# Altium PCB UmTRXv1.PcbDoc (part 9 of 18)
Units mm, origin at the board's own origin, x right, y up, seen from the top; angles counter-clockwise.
Board outline 172 x 113 mm, 6 copper layers (Top Layer, GND, MidLayer1, Mid-Layer 2, InternalPlane2, Bottom Layer); 766 components, 613 nets, 3008 pads, 1360 vias.
Unrouted connection lines stored in the file: 2.
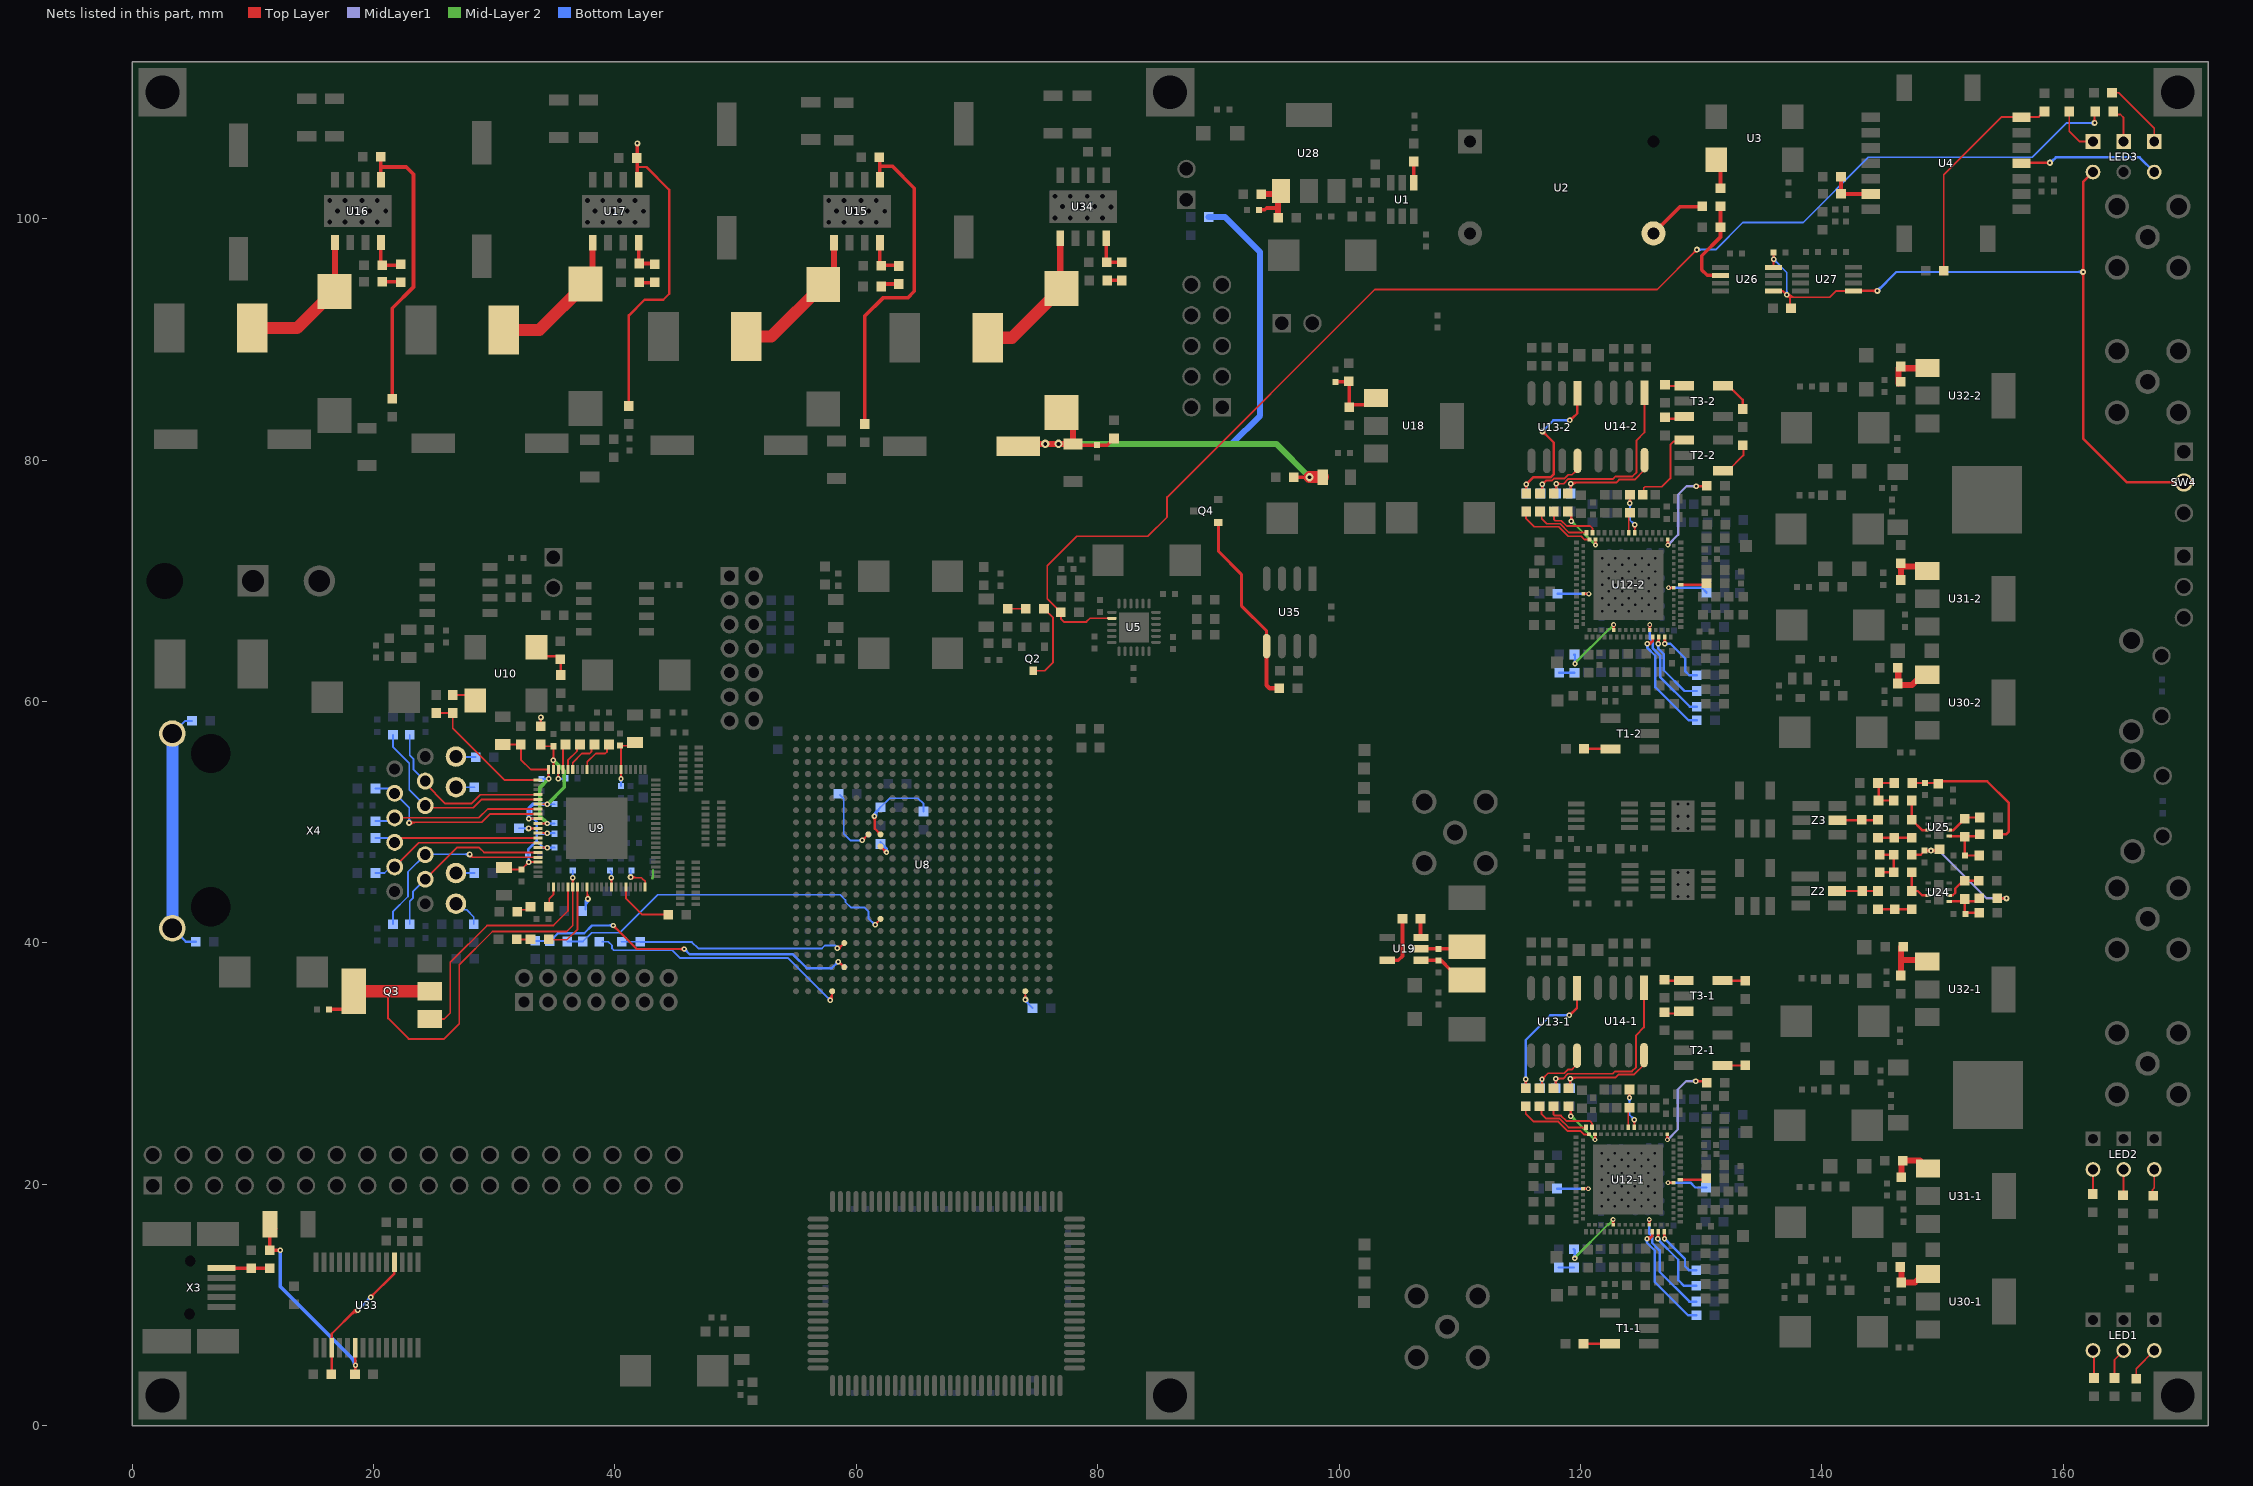
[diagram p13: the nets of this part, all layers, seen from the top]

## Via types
v1: diameter 0.45, hole 0.2, Top Layer to Bottom Layer, tented both sides, 554 vias
v2: diameter 0.5, hole 0.2, Top Layer to Bottom Layer, tented both sides, 468 vias
v3: diameter 0.7, hole 0.3, Top Layer to Bottom Layer, tented both sides, 206 vias
v4: diameter 0.4, hole 0.2, Top Layer to Bottom Layer, tented both sides, 82 vias
v5: diameter 0.8, hole 0.3, Top Layer to Bottom Layer, tented both sides, 16 vias
v6: diameter 0.6, hole 0.25, Top Layer to Bottom Layer, tented both sides, 16 vias
v7: diameter 0.5, hole 0.3, Top Layer to Bottom Layer, tented both sides, 8 vias
v8: diameter 0.7, hole 0.3, Top Layer to Bottom Layer, 4 vias
v9: diameter 0.6, hole 0.3, Top Layer to Bottom Layer, tented both sides, 4 vias
v10: diameter 0.5, hole 0.2, Top Layer to Bottom Layer, 2 vias

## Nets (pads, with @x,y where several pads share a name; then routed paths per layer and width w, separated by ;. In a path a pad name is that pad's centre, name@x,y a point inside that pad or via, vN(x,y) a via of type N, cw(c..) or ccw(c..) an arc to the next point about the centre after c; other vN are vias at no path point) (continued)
NetC107-2_2: C107-2.2 T2-2.3 | length 7.2
  Top Layer w0.15: C107-2.2@125.15,77.15 125.25,77.25 125.25,77.704 125.346,77.8 126.75,77.8 127.45,78.5 127.45,81.3 127.7,81.55 128.48,81.55 T2-2.3@128.6,81.67
NetC110-1_1: C110-1.1 T1-1.4 | length 2.2
  Top Layer w0.2: C110-1.1@120.257,6.788 T1-1.4@122.461,6.788
NetC110-2_1: C110-2.1 T1-2.4 | length 2.2
  Top Layer w0.2: C110-2.1@120.296,56.08 T1-2.4@122.5,56.08
NetC111-1_2: C111-1.2 T2-1.6 | length 1.9
  Top Layer w0.15: T2-1.6@131.761,29.838 131.781,29.858 C111-1.2@133.661,29.858
NetC111-2_2: C111-2.2 T2-2.6 | length 3
  Top Layer w0.15: T2-2.6@131.8,79.13 131.82,79.15 132.25,79.15 133.5,80.4 C111-2.2@133.5,81.2
NetC112-1_1: C112-1.1 T3-1.4 | length 1.9
  Top Layer w0.2: T3-1.4@131.761,36.878 133.641,36.878 C112-1.1@133.661,36.858
NetC112-2_1: C112-2.1 T3-2.4 | length 2.8
  Top Layer w0.2: T3-2.4@131.8,86.17 132.28,86.17 133.45,85 C112-2.1@133.45,84.3
NetC113_1: C113.1 C131.1 C261.1 C269.1 L34.1 L35.1 R170.1 R172.1 | length 75.3
  Top Layer w0.3: C261.1@78.054,81.246 C113.1@79.946,81.246 80.796,81.246 R170.1@81.35,81.8 ; C269.1@96.25,78.6 v3(97.55,78.6) ; v3@97.409,78.459 ccw(c97.067,78.117) 97.067,78.6 ccw(c97.067,79.083) v3@97.409,78.741
  Top Layer w0.5: C131.1@73.4,81.15 73.6,81.35 C261.1@77.95,81.35 ; L35.1@77,83.95 77.95,83 C261.1@77.95,81.35 ; C261.1@78.054,81.246 C261.1@77.95,81.35
  Top Layer w1: v3(97.55,78.6) L34.1@98.65,78.6
  Mid-Layer 2 w0.5: v3(75.65,81.35) v3(76.75,81.35) 94.8,81.35 v3(97.55,78.6)
  Bottom Layer w0.5: v3(75.65,81.35) v3(76.75,81.35) 91.1,81.35 93.45,83.7 93.45,97.25 90.55,100.15 R172.1@89.2,100.15
NetC128_1: C128.1 C132.1 U15.4 | length 3.4
  Top Layer w0.3: U15.4@61.943,98.079 61.943,96.19 61.965,96.168 C128.1@61.984,96.187 ; C128.1@61.994,96.15 C132.1@63.45,96.15
NetC129_1: C129.1 C133.1 U16.4 | length 3.3
  Top Layer w0.3: C129.1@20.605,96.25 U16.4@20.605,98.095 ; C129.1@20.705,96.15 C133.1@22.2,96.15
NetC130_1: C130.1 C134.1 U17.4 | length 3.4
  Top Layer w0.3: C130.1@41.9,96.3 C130.1@41.953,96.3 ; U17.4@41.953,98.242 C130.1@41.953,96.3 ; C130.1@42,96.25 41.953,96.297 C130.1@41.953,96.3 ; C134.1@43.3,96.3 C130.1@42,96.3 C130.1@41.953,96.3
NetC132_2: C132.2 R131.1 | length 1.3
  Top Layer w0.3: R131.1@62.15,94.6 C132.2@63.4,94.6
NetC133_2: C133.2 R132.1 | length 1.3
  Top Layer w0.3: R132.1@20.751,94.8 C133.2@22.1,94.8
NetC134_2: C134.2 R133.1 | length 1.3
  Top Layer w0.3: R133.1@41.95,94.7 C134.2@43.3,94.7
NetC135_1: C135.1 R134.2 R135.1 U18.1 | length 5.8
  Top Layer w0.3: C135.1@99.7,86.5 100.75,86.5 R135.1@100.8,86.55 100.85,86.5 R134.2@100.85,84.4 101.05,84.6 102.5,84.6 U18.1@103.05,85.15
NetC149_2: C149.2 L39.2 U19.2 | length 4.1
  Top Layer w0.3: U19.2@106.783,39.513 109.795,39.513 L39.2@110.55,40.268
NetC155_1: C155.1 L44.1 U19.1 | length 4.1
  Top Layer w0.3: U19.1@106.783,38.563 108.437,38.563 109.218,37.782 L44.1@110.55,37.782
NetC170_1: C170.1 U19.5 | length 4.5
  Top Layer w0.3: U19.5@103.989,38.563 104.913,38.563 105.25,38.9 C170.1@105.25,42
NetC170_2: C170.2 U19.3 | length 1.6
  Top Layer w0.3: C170.2@106.75,42 106.75,40.496 U19.3@106.783,40.463
NetC214_2: C214.2 C236.1 C237.1 C238.1 C239.1 C280.1 C284.1 C286.2 L46.1 Q3.2 Q3.4 U9.6 U9.19 U9.48 U9.56 U9.63 | length 55.2
  Top Layer w0.1: U9.63@42.5,44.625 U9.63@42.5,44.975
  Top Layer w0.15: 21.2,36 21.2,33.75 22.9,32.05 25.85,32.05 27.1,33.3 27.1,38.2 29.85,40.95 36,40.95 36.5,41.45 U9.48@36.5,44.625 v1(36.5,45.4) ; v2@33.726,58.576 cw(c33.428,58.278) 33.85,58.278 cw(c34.272,58.278) v2@33.974,58.576 ; L46.1@33.85,57.95 33.85,58.65 33.8,58.7 v2(33.85,58.7) ; v1@35.194,53.706 ccw(c34.938,53.962) 35.3,53.962 ccw(c35.662,53.962) v1@35.406,53.706 ; v1(35.3,53.6) U9.19@35.3,54.375 ; v1@36.394,45.294 cw(c36.138,45.038) 36.5,45.038 cw(c36.862,45.038) v1@36.606,45.294 ; v1@39.594,45.294 cw(c39.338,45.038) 39.7,45.038 cw(c40.062,45.038) v1@39.806,45.294 ; U9.56@39.7,44.625 v1(39.7,45.4) ; v1@40.394,53.706 ccw(c40.138,53.962) 40.5,53.962 ccw(c40.862,53.962) v1@40.606,53.706 ; v1(40.5,53.6) U9.6@40.5,54.375 40.5,56.25 C286.2@40.4,56.35 41.4,56.35 C284.1@41.65,56.6 ; v2(41.3,45.45) 41.3,45.4 42.199,45.4 42.274,45.325 ; v2@41.424,45.326 cw(c41.602,45.148) 41.602,45.4 ; v2@41.424,45.574 ccw(c41.843,45.993) 41.843,45.4 ; 42.275,45.325 42.5,45.1 U9.63@42.5,44.975
  Top Layer w0.3: C214.2@16.3,34.5 Q3.4@17.5,34.5
  Top Layer w1: Q3.4@18.35,36 21.2,36 Q3.2@24.65,36
  Mid-Layer 2 w0.2: 43.1,45.35 43.15,45.4 43.15,46.05
  Bottom Layer w0.15: v1(35.3,53.6) 35.85,53.6 C237.1@35.9,53.65 ; v1@35.406,53.494 cw(c35.662,53.238) 35.662,53.6 cw(c35.662,53.962) v1@35.406,53.706 ; v1@36.394,45.506 ccw(c36.138,45.762) 36.5,45.762 ccw(c36.862,45.762) v1@36.606,45.506 ; v1(36.5,45.4) C238.1@36.5,46 ; v1@39.594,45.506 ccw(c39.338,45.762) 39.7,45.762 ccw(c40.062,45.762) v1@39.806,45.506 ; C239.1@39.6,46 39.7,45.9 v1(39.7,45.4) ; v1@40.394,53.494 cw(c40.138,53.238) 40.5,53.238 cw(c40.862,53.238) v1@40.606,53.494 ; C236.1@40.5,53 v1(40.5,53.6) ; v2@41.176,45.574 ccw(c40.878,45.872) 41.3,45.872 ccw(c41.723,45.873) v2@41.424,45.574 ; v2(41.3,45.45) C280.1@41.3,46.05
NetC240_1: C240.1 C241.1 C242.1 C243.1 C244.1 C245.1 C285.1 C287.2 L46.2 U9.20 U9.27 U9.30 U9.33 U9.36 U9.39 | length 33.4
  Top Layer w0.15: C285.1@30.8,46.05 30.85,46.1 C287.2@32.25,46.1 v1(32.85,46.7) U9.39@33.625,46.7 ; v1@32.7,46.7 cw(c32.338,46.7) 32.594,46.444 cw(c32.85,46.188) v1@32.85,46.55 ; v1(32.85,50.3) U9.30@33.625,50.3 ; v1@32.956,46.594 cw(c33.212,46.338) 33.212,46.7 cw(c33.212,47.062) v1@32.956,46.806 ; v1@32.956,50.194 cw(c33.212,49.938) 33.212,50.3 cw(c33.212,50.662) v1@32.956,50.406 ; U9.36@33.625,47.9 v1(34.4,47.9) ; U9.33@33.625,49.1 v1(34.4,49.1) ; U9.27@33.625,51.5 v1(34.4,51.5) ; L46.2@33.85,56.45 34,56.3 C240.1@34.9,56.3 v1(34.9,55.15) U9.20@34.9,54.375 ; v1@34.294,47.794 ccw(c34.038,47.538) 34.038,47.9 ccw(c34.038,48.262) v1@34.294,48.006 ; v1@34.294,48.994 ccw(c34.038,48.738) 34.038,49.1 ccw(c34.038,49.462) v1@34.294,49.206 ; v1@34.294,51.394 ccw(c34.038,51.138) 34.038,51.5 ccw(c34.038,51.862) v1@34.294,51.606 ; v1@34.794,55.044 cw(c34.538,54.788) 34.9,54.788 cw(c35.262,54.788) v1@35.006,55.044 ; v1@34.794,55.256 ccw(c34.538,55.512) 34.9,55.512 ccw(c35.262,55.512) v1@35.006,55.256
  Mid-Layer 2 w0.3: v1(34.4,51.5) 35.8,52.9 35.8,54.25 v1(34.9,55.15)
  Bottom Layer w0.15: v1@32.744,46.806 ccw(c32.488,47.062) 32.85,47.062 ccw(c33.212,47.062) v1@32.956,46.806 ; v1@32.744,50.406 ccw(c32.488,50.662) 32.85,50.662 ccw(c33.212,50.662) v1@32.956,50.406 ; C245.1@32.8,47.3 32.85,47.25 v1(32.85,46.7) ; v1(32.85,50.3) 32.85,50.75 C242.1@32.9,50.8 ; v1(34.4,47.9) C244.1@35,47.9 ; v1(34.4,49.1) C243.1@35,49.1 ; v1(34.4,51.5) C241.1@35,51.5 ; v1@34.506,47.794 cw(c34.762,47.538) 34.762,47.9 cw(c34.762,48.262) v1@34.506,48.006 ; v1@34.506,48.994 cw(c34.762,48.738) 34.762,49.1 cw(c34.762,49.462) v1@34.506,49.206 ; v1@34.506,51.394 cw(c34.762,51.138) 34.762,51.5 cw(c34.762,51.862) v1@34.506,51.606
  Bottom Layer w0.2: C245.1@32.8,47.3 32.8,47.75 33.5,48.45 ; v1(32.85,50.3) 33.25,50.3 33.5,50.05 33.5,49.05 ; v1@32.938,50.212 cw(c33.152,49.998) 33.152,50.3 cw(c33.152,50.602) v1@32.938,50.388 ; 33.978,49.05 ccw(c33.978,49.522) v1@34.312,49.188 ; v1@34.312,47.812 ccw(c34.098,47.598) 34.098,47.9 ccw(c34.098,48.202) v1@34.312,47.988 ; v1(34.4,47.9) 34.05,47.9 33.5,48.45 ; v1(34.4,49.1) 34.35,49.05 33.5,49.05 ; 33.5,48.45 33.5,49.05
  Bottom Layer w0.3: C242.1@32.9,50.8 32.9,51.2 33.2,51.5 v1(34.4,51.5)
NetC266_1: C266.1 C267.1 U34.4 | length 3.3
  Top Layer w0.3: U34.4@80.703,98.392 80.703,96.447 C266.1@80.75,96.4 C267.1@82,96.4
NetC267_2: C267.2 R169.1 | length 1.2
  Top Layer w0.3: R169.1@80.8,94.9 C267.2@82,94.9
NetC278_1: C278.1 R5.2 R8.1 U28.1 | length 5.4
  Top Layer w0.3: C278.1@93.35,100.75 93.85,100.75 94,100.9 94.95,100.9
  Top Layer w0.5: R5.2@93.55,102.05 U28.1@94.95,102.05 ; R8.1@94.95,100.1 94.95,100.9 U28.1@94.95,102.05 ; U28.1@95.2,102.3 U28.1@94.95,102.05
NetC281_1: C281.1 C282.1 C283.1 L45.2 U9.21 U9.31 | length 14.7
  Top Layer w0.15: C283.1@30.7,56.45 L45.2@32.2,56.45 32.2,55.2 33.025,54.375 U9.21@34.5,54.375 v1(34.5,53.6) ; U9.31@33.625,49.9 v1(34.4,49.9) ; v1@34.294,49.794 ccw(c34.038,49.538) 34.038,49.9 ccw(c34.038,50.262) v1@34.294,50.006 ; v1@34.394,53.706 ccw(c34.138,53.962) 34.5,53.962 ccw(c34.862,53.962) v1@34.606,53.706
  Mid-Layer 2 w0.3: v1(34.4,49.9) 33.75,50.55 33.75,52.85 v1(34.5,53.6)
  Bottom Layer w0.15: C281.1@33.9,53.6 v1(34.5,53.6) ; v1@34.394,53.494 ccw(c34.138,53.238) 34.138,53.6 ccw(c34.138,53.962) v1@34.394,53.706 ; v1(34.4,49.9) C282.1@35,49.9 ; v1@34.506,49.794 cw(c34.762,49.538) 34.762,49.9 cw(c34.762,50.262) v1@34.506,50.006
NetC298_2: C298.2 L49.2 R143.1 R147.1 | length 14
  Top Layer w0.2: R147.1@147.401,47.306 148.201,47.306 148.551,47.656 v2(149.05,47.656) 149.651,47.656 L49.2@149.751,47.756 ; v2@148.944,47.55 ccw(c148.688,47.294) 148.688,47.656 ccw(c148.688,48.018) v2@148.944,47.762 ; v2@149.156,47.55 cw(c149.412,47.294) 149.412,47.656 cw(c149.412,48.018) v2@149.156,47.762 ; R143.1@154.55,43.7 v2(155.3,43.7) ; v2@155.194,43.594 ccw(c154.938,43.338) 154.938,43.7 ccw(c154.938,44.062) v2@155.194,43.806
  MidLayer1 w0.2: v2(149.05,47.656) 149.694,47.656 153.65,43.7 v2(155.3,43.7) ; v2@149.156,47.55 cw(c149.412,47.294) 149.412,47.656 cw(c149.412,48.018) v2@149.156,47.762 ; v2@155.194,43.594 ccw(c154.938,43.338) 154.938,43.7 ccw(c154.938,44.062) v2@155.194,43.806
NetC299_2: C299.2 L50.2 R145.1 R148.1 | length 12.3
  Top Layer w0.2: R148.1@147.501,53.256 C299.2@148.551,53.256 149.401,53.256 L50.2@149.651,53.006 ; L50.2@149.65,53.2 149.85,53.4 153.7,53.4 155.5,51.6 155.5,49.25 155.25,49 R145.1@154.6,49
NetC300_1: C300.1 R141.2 R144.2 | length 2.8
  Top Layer w0.2: R141.2@144.651,42.806 R144.2@146.051,42.806 C300.1@147.451,42.806
NetC300_2: C300.2 L51.2 U24.7 | length 3.1
  Top Layer w0.2: L51.2@147.451,45.856 C300.2@147.451,44.306 147.944,44.306 148.3,43.95 U24.7@148.825,43.95
NetC301_1: C301.1 R142.2 R146.2 | length 2.8
  Top Layer w0.2: R142.2@144.651,48.706 R146.2@146.001,48.706 C301.1@147.451,48.706
NetC301_2: C301.2 L52.2 U25.7 | length 3.3
  Top Layer w0.2: L52.2@147.451,51.806 C301.2@147.451,50.206 148.301,49.356 U25.7@148.826,49.356
NetC302_1: C302.1 C304.1 L51.1 R147.2 | length 3.7
  Top Layer w0.2: C302.1@144.801,45.856 L51.1@145.951,45.856 145.951,47.299 R147.2@145.95,47.3 145.944,47.306 C304.1@144.801,47.306
NetC303_1: C303.1 C305.1 L52.1 R148.2 | length 4.1
  Top Layer w0.2: L52.1@145.951,51.806 C303.1@144.701,51.806 144.701,53.206 C305.1@144.651,53.256 R148.2@146.001,53.256
NetC306_2: C306.2 C310.1 L53.1 R143.2 U24.1 | length 5
  Top Layer w0.2: U24.1@150.575,43.45 L53.1@151.85,43.45 ; L53.1@151.85,43.65 L53.1@151.85,43.45 ; C310.1@153.05,42.5 152,42.5 C306.2@151.9,42.4 151.85,42.45 L53.1@151.85,43.45 ; R143.2@153.05,43.7 152.8,43.45 L53.1@151.85,43.45
NetC307_1: C307.1 L53.2 U24.2 | length 3.1
  Top Layer w0.2: U24.2@150.575,43.95 150.85,43.95 151.05,44.15 151.05,44.5 151.7,45.15 L53.2@151.85,45.15 C307.1@153,45.15
NetC308_2: C308.2 C311.1 L54.1 R145.2 U25.1 | length 5.3
  Top Layer w0.2: U25.1@150.576,48.856 152.956,48.856 R145.2@153.1,49 ; L54.1@151.85,48.8 151.85,47.257 C308.2@151.851,47.256 151.857,47.25 C311.1@153.05,47.25
NetC309_1: C309.1 L54.2 U25.2 | length 3
  Top Layer w0.2: U25.2@150.576,49.356 150.906,49.356 L54.2@151.85,50.3 151.95,50.4 C309.1@153.1,50.4
NetC313_2: C313.2 LED3.4 R153.2 SW4.2 U26.5 U26.8 U27.5 | length 71.7
  Top Layer w0.15: C313.2@135.9,97.15 136.008,97.042 v1(136.008,96.65) U26.8@136.008,95.97 ; v1@135.902,96.544 cw(c135.645,96.288) 136.008,96.288 cw(c136.37,96.288) v1@136.114,96.544 ; v1@135.902,96.756 ccw(c135.645,97.012) 136.008,97.012 ccw(c136.37,97.012) v1@136.114,96.756 ; U26.5@136.008,94.021 136.779,94.021 v1(137.1,93.7) ; v1@136.95,93.7 ccw(c136.588,93.7) 136.844,93.956 ccw(c137.1,94.212) v1@137.1,93.85 ; v1@137.128,93.553 cw(c137.164,93.365) 137.3,93.5 ; v1@137.206,93.806 ccw(c137.945,94.545) 137.945,93.5 ; v1@137.247,93.672 ccw(c137.435,93.636) 137.3,93.5 ; R153.2@137.36,92.8 137.36,93.46 ; 137.583,93.5 cw(c137.583,94.183) v1(137.1,93.7) ; U27.5@142.621,94.036 141.186,94.036 140.65,93.5 137.3,93.5 ; v1(137.1,93.7) 137.3,93.5
  Top Layer w0.2: U27.5@142.621,94.036 v2(144.6,94.036) ; v2@144.494,93.93 ccw(c144.238,93.674) 144.238,94.036 ccw(c144.238,94.398) v2@144.494,94.142 ; v2@161.544,95.494 cw(c161.288,95.238) 161.65,95.238 cw(c162.012,95.238) v2@161.756,95.494 ; v2@161.544,95.706 ccw(c161.288,95.962) 161.65,95.962 ccw(c162.012,95.962) v2@161.756,95.706 ; LED3.4@162.47,103.88 161.65,103.06 v2(161.65,95.6) 161.65,81.8 165.29,78.16 SW4.2@170,78.16
  Bottom Layer w0.15: v1@136.008,96.5 cw(c136.008,96.138) 136.264,96.394 cw(c136.52,96.65) v1@136.158,96.65 ; v1(136.008,96.65) 137.1,95.558 v1(137.1,93.7) ; v1@136.994,93.806 ccw(c136.738,94.062) 137.1,94.062 ccw(c137.462,94.062) v1@137.206,93.806
  Bottom Layer w0.2: v2(144.6,94.036) 146.164,95.6 v2(161.65,95.6) ; v2@144.6,94.186 ccw(c144.6,94.548) 144.856,94.292 ccw(c145.112,94.036) v2@144.75,94.036 ; v2@161.544,95.494 ccw(c161.288,95.238) 161.288,95.6 ccw(c161.288,95.962) v2@161.544,95.706
NetC316_2: C316.2 L55.1 X3.1 | length 4
  Top Layer w0.3: X3.1@7.4,13.05 C316.2@9.85,13.05 L55.1@11.4,13.05
NetC317_1: C317.1 C318.2 L55.2 U33.20 | length 19.1
  Top Layer w0.2: v1@18.412,4.912 cw(c18.259,4.759) 18.475,4.759 ; v1@18.412,5.088 ccw(c18.259,5.241) 18.475,5.241 ; C318.2@18.45,4.25 18.475,4.275 U33.20@18.475,6.45 ; C318.2@18.475,4.638 cw(c18.862,4.638) v1@18.588,4.912 ; 18.475,5.362 ccw(c18.862,5.362) v1@18.588,5.088
  Top Layer w0.3: C317.1@11.9,16.325 11.4,15.825 L55.2@11.4,14.55 v1(12.25,14.55)
  Bottom Layer w0.3: v1(12.25,14.55) 12.25,11.55 18.45,5.35 18.45,5.05 v1(18.5,5) ; 18.16,5.64 cw(c17.52,5) v1@18.425,5 ; 18.45,5.302 ccw(c18.802,5.302) v1@18.553,5.053
NetC319_2: C319.2 U33.4 U33.17 | length 14.3
  Top Layer w0.2: C319.2@16.5,4.25 16.525,4.275 U33.17@16.525,6.45 16.525,7.625 18.45,9.55 ; 18.06,9.16 cw(c18.7,8.52) v1@18.7,9.425 ; 18.401,9.501 cw(c18.7,9.203) v1@18.7,9.625 ; v1@18.6,9.475 ccw(c18.45,9.363) 18.45,9.55 ; v1@18.6,9.625 cw(c18.45,9.737) 18.45,9.55 ; v1(18.7,9.55) 18.45,9.55 ; v1(19.75,10.65) 21.725,12.625 U33.4@21.725,13.55 ; v1@19.75,10.775 ccw(c19.75,11.077) 19.963,10.863 ccw(c20.177,10.65) v1@19.875,10.65
  Bottom Layer w0.2: v1(18.7,9.55) 18.7,9.6 v1(19.75,10.65) ; v1@18.825,9.55 cw(c19.247,9.55) 18.949,9.849 ; v1@19.625,10.65 cw(c19.323,10.65) 19.537,10.437 cw(c19.75,10.223) v1@19.75,10.525
NetD1_2: D1.2 L36.2 U15.1 | length 12
  Top Layer w0.5: L36.2@57.25,94.55 58.153,95.453 U15.1@58.153,98.029
  Top Layer w1: D1.2@50.879,90.25 52.95,90.25 L36.2@57.25,94.55
NetD2_2: D2.2 L37.2 U16.1 | length 12.3
  Top Layer w0.5: L37.2@16.793,94.093 U16.1@16.793,98.042
  Top Layer w1: D2.2@9.929,90.95 13.65,90.95 L37.2@16.793,94.093 ; L37.2@16.55,93.2 L37.2@16.55,93.4
NetD3_2: D3.2 L38.2 U17.1 | length 12
  Top Layer w0.5: L38.2@37.55,94.6 38.153,95.203 U17.1@38.153,98.029
  Top Layer w1: D3.2@30.779,90.8 33.75,90.8 L38.2@37.55,94.6
NetD4_2: D4.2 L35.2 U34.1 | length 12
  Top Layer w0.3: L35.2@76.893,94.357 L35.2@77,94.25
  Top Layer w0.5: L35.2@76.893,94.357 U34.1@76.893,98.392
  Top Layer w1: D4.2@70.879,90.15 72.9,90.15 L35.2@77,94.25
NetL32-1_2: L32-1.2 T3-1.1 | length 2
  Top Layer w0.2: L32-1.2@126.661,34.158 128.381,34.158 T3-1.1@128.561,34.338
NetL32-2_2: L32-2.2 T3-2.1 | length 2
  Top Layer w0.2: L32-2.2@126.7,83.45 128.42,83.45 T3-2.1@128.6,83.63
NetL33-1_2: L33-1.2 T3-1.3 | length 1.9
  Top Layer w0.2: L33-1.2@126.661,36.858 128.541,36.858 T3-1.3@128.561,36.878
NetL33-2_2: L33-2.2 T3-2.3 | length 1.9
  Top Layer w0.2: L33-2.2@126.7,86.15 128.58,86.15 T3-2.3@128.6,86.17
NetLED1_4: LED1.4 R35.2 | length 2.3
  Top Layer w0.15: LED1.4@162.47,6.23 162.55,6.15 R35.2@162.55,3.95
NetLED1_5: LED1.5 R34.2 | length 2.6
  Top Layer w0.15: R34.2@164.25,3.95 164.25,5.47 LED1.5@165.01,6.23
NetLED1_6: LED1.6 R33.2 | length 3
  Top Layer w0.15: R33.2@166.05,3.9 166.05,4.73 LED1.6@167.55,6.23
NetLED2_4: LED2.4 R38.2 | length 2
  Top Layer w0.15: R38.2@162.45,19.2 162.47,19.22 LED2.4@162.47,21.23
NetLED2_5: LED2.5 R37.2 | length 2.2
  Top Layer w0.15: R37.2@164.95,19.1 165.01,19.16 LED2.5@165.01,21.23
NetLED2_6: LED2.6 R36.2 | length 2.3
  Top Layer w0.15: R36.2@167.45,19.05 167.4,19.1 167.4,19.55 167.55,19.7 LED2.6@167.55,21.23
NetLED3_1: LED3.1 R1.2 | length 5.8
  Top Layer w0.15: R1.2@164.05,110.45 164.6,110.45 167.55,107.5 LED3.1@167.55,106.42
NetLED3_2: LED3.2 R13.1 | length 2.9
  Top Layer w0.15: R13.1@164.15,108.65 164.75,108.65 165.01,108.39 LED3.2@165.01,106.42
NetLED3_3: LED3.3 R162.2 | length 4
  Top Layer w0.15: R162.2@160.5,108.9 160.5,107.25 161.33,106.42 LED3.3@162.47,106.42
NetLED3_6: LED3.6 U4.4 | length 12.7
  Top Layer w0.2: U4.4@156.65,104.65 v2(158.9,104.65) ; v2@158.794,104.544 ccw(c158.538,104.288) 158.538,104.65 ccw(c158.538,105.012) v2@158.794,104.756
  Bottom Layer w0.2: v2(158.9,104.65) 158.95,104.65 159.4,105.1 166.33,105.1 LED3.6@167.55,103.88 ; v2@158.9,104.8 ccw(c158.9,105.283) 159.241,104.941 ; v2@159.05,104.65 cw(c159.291,104.65) 159.121,104.821
NetLED4_1: LED4.1 Q2.3 | length 6.7
  Top Layer w0.15: Q2.3@74.65,62.55 75.6,62.55 76.3,63.25 76.3,66.95 LED4.1@75.55,67.7
NetLED4_2: LED4.2 R29.2 | length 1.5
  Top Layer w0.15: R29.2@72.55,67.7 LED4.2@74.05,67.7
NetLED5_1: LED5.1 R55.1 | length 1.1
  Top Layer w0.15: LED5.1@31.9,42.6 32.05,42.75 32.75,42.75 R55.1@32.9,42.9
NetLED6_1: LED6.1 R57.1 | length 1.2
  Top Layer w0.15: LED6.1@31.85,40.3 R57.1@33,40.3
NetQ3_1: Q3.1 U9.47 | length 19.6
  Top Layer w0.15: Q3.1@24.65,33.7 25.85,33.7 26.35,34.2 26.35,38.4 29.4,41.45 34.9,41.45 36.1,42.65 U9.47@36.1,44.625
NetQ4_1: Q4.1 R174.2 U35.5 | length 16.5
  Top Layer w0.25: Q4.1@90,74.85 90,72.45 91.9,70.55 91.9,67.95 93.995,65.855 U35.5@93.995,64.603
  Top Layer w0.35: U35.5@93.995,64.603 93.995,61.355 94.25,61.1 R174.2@95.2,61.1
NetR4_1: R4.1 U1.1 | length 1.8
  Top Layer w0.3: R4.1@106.189,104.75 106.189,102.986 U1.1@106.19,102.985
NetR6_1: R6.1 U2.8 | length 5.4
  Top Layer w0.3: U2.8@126.3,98.55 U2.8@126.05,98.8 128.25,101 R6.1@130.2,101
NetR6_2: R6.2 R7.2 R12.2 U26.2 | length 7.7
  Top Layer w0.3: R7.2@131.6,101.05 R12.2@131.6,99.3 131.6,98.5 130.05,96.95 130.05,95.771 130.5,95.321 U26.2@131.608,95.321
NetR7_1: R7.1 U3.3 | length 1.4
  Top Layer w0.3: R7.1@131.6,102.55 U3.3@131.6,103.944
NetR9_2: R9.2 R10.1 U4.15 | length 3.9
  Top Layer w0.3: R9.2@141.586,103.503 141.593,103.496 R10.1@141.593,102.077 141.609,102.06 U4.15@144.05,102.06
NetR11_2: R11.2 R13.2 U5.8 | length 115.9
  Top Layer w0.15: U5.8@81.175,66.9 79.362,66.9 79.062,66.6 77.2,66.6 76.95,66.85 R11.2@76.95,67.4 76.15,68.2 75.825,68.525 75.825,71.275 78.25,73.7 84.15,73.7 85.75,75.3 85.75,76.95 102.95,94.15 126.35,94.15 v2(129.65,97.45) ; v2@129.475,97.45 cw(c129.053,97.45) 129.351,97.151 cw(c129.65,96.853) v2@129.65,97.275 ; v2@162.476,108.074 ccw(c162.178,108.372) 162.6,108.372 ccw(c163.022,108.372) v2@162.724,108.074 ; v2(162.6,107.95) 162.6,108.85 R13.2@162.65,108.9
  Bottom Layer w0.15: v2(129.65,97.45) 131.2,97.45 133.45,99.7 138.45,99.7 143.85,105.1 157.45,105.1 160.3,107.95 v2(162.6,107.95) ; v2@129.774,97.326 cw(c130.072,97.028) 130.072,97.45 cw(c130.072,97.872) v2@129.774,97.574 ; v2@162.476,107.826 ccw(c162.178,107.528) 162.178,107.95 ccw(c162.178,108.372) v2@162.476,108.074
NetR14_2: R14.2 R18.2 U8.C18 | length 30.8
  Top Layer w0.2: v1@39.85,41.325 cw(c39.85,41.023) 40.063,41.237 cw(c40.277,41.45) v1@39.975,41.45 ; v1(39.85,41.45) 41.8,39.5 v1(45.75,39.5) ; v1@45.662,39.412 ccw(c45.448,39.198) 45.448,39.5 ccw(c45.448,39.802) v1@45.662,39.588 ; v1@58.5,38.325 cw(c58.5,37.903) 58.799,38.201 ; v1(58.5,38.45) 58.55,38.5 58.55,38.45 U8.C18@59,38
  Bottom Layer w0.15: R18.2@33.388,40.171 34.565,40.171 R14.2@34.604,40.133
  Bottom Layer w0.2: R14.2@34.604,40.133 35.271,40.8 37.45,40.8 38.1,41.45 v1(39.85,41.45) ; v1@39.762,41.362 ccw(c39.548,41.148) 39.548,41.45 ccw(c39.548,41.752) v1@39.762,41.538 ; v1@45.75,39.375 cw(c45.75,39.073) 45.963,39.287 cw(c46.177,39.5) v1@45.875,39.5 ; v1(45.75,39.5) 46.2,39.05 54.75,39.05 55.886,37.914 57.964,37.914 v1(58.5,38.45) ; v1@58.375,38.45 cw(c58.073,38.45) 58.287,38.237 cw(c58.5,38.023) v1@58.5,38.325
NetR15_2: R15.2 R20.1 U8.G15 | length 30.4
  Top Layer w0.15: v1(61.55,41.5) 61.55,41.55 U8.G15@62,42 ; v1@61.55,41.65 ccw(c61.55,41.891) 61.721,41.721 ; v1@61.7,41.5 cw(c62.183,41.5) U8.G15@61.841,41.841
  Bottom Layer w0.15: R20.1@36.036,40.12 R15.2@37.341,40.12 38.071,40.85 40.4,40.85 43.55,44 58.65,44 59.1,43.55 59.1,43.384 59.534,42.95 60.666,42.95 61,42.616 61,42.05 v1(61.55,41.5) ; v1@61.4,41.5 ccw(c61.038,41.5) 61.294,41.756 ccw(c61.55,42.012) v1@61.55,41.65
NetR16_2: R16.2 U8.A19 | length 23.8
  Top Layer w0.15: v1@57.744,35.356 ccw(c57.126,35.974) U8.A19@58,35.974 ; v1@57.862,35.399 ccw(c57.877,35.573) 58,35.45 ; v1@57.982,35.322 cw(c58.076,35.374) 58,35.45 ; 58,35.612 cw(c57.488,35.612) v1(57.85,35.25) 57.85,35.3 58,35.45 ; U8.A19@58,36 58,35.45
  Bottom Layer w0.15: R16.2@38.94,40.12 38.959,40.1 39.45,40.1 39.75,39.8 39.75,39.55 39.9,39.4 44.75,39.4 45.4,38.75 54.35,38.75 v1(57.85,35.25) ; v1@57.7,35.25 ccw(c57.338,35.25) 57.594,35.506 ccw(c57.85,35.762) v1@57.85,35.4
NetR17_2: R17.2 R19.2 U8.E18 | length 20.3
  Top Layer w0.15: v1(58.428,39.552) 58.43,39.55 58.55,39.55 U8.E18@59,40 ; v1@58.5,39.7 ccw(c58.5,40.183) U8.E18@58.841,39.841 ; v1@58.65,39.55 cw(c58.891,39.55) 58.721,39.721
  Bottom Layer w0.15: R17.2@40.55,40.1 R19.2@42.1,40.1 42.125,40.075 46.375,40.075 46.9,39.55 57.145,39.55 57.22,39.625 57.384,39.789 58.261,39.789 ; v1@58.35,39.557 ccw(c58.044,39.572) 58.261,39.789 ; v1(58.428,39.552) 58.498,39.552 58.261,39.789 ; v1@58.493,39.7 cw(c58.478,40.006) 58.261,39.789
NetR21_2: R21.2 U8.P16 | length 6.9
  Top Layer w0.15: v1(60.5,48.5) U8.P16@61,49 ; v1@60.5,48.65 ccw(c60.5,49.012) 60.756,48.756 ccw(c61.012,48.5) v1@60.65,48.5
  Bottom Layer w0.15: R21.2@58.65,52.25 58.95,51.95 58.95,49.05 59.5,48.5 v1(60.5,48.5) ; v1@60.394,48.394 ccw(c60.138,48.138) 60.138,48.5 ccw(c60.138,48.862) v1@60.394,48.606
NetR23_2: R23.2 U8.N15 | length 4.4
  Top Layer w0.2: U8.N15@62,48 v1(62.5,47.5) ; v1@62.35,47.5 ccw(c61.988,47.5) 62.244,47.756 ccw(c62.5,48.012) v1@62.5,47.65
  Bottom Layer w0.2: R23.2@62.34,48.01 cw(c61.832,47.503) v1@62.55,47.5 ; v1@62.35,47.501 ccw(c61.155,47.505) 62,48.35 62.5,47.85 ; v1@62.397,47.609 ccw(c62.167,47.85) 62.5,47.85 ; v1(62.5,47.5) 62.5,47.85 ; v1@62.603,47.609 cw(c62.833,47.85) 62.5,47.85
NetR24_2: R24.2 R67.2 U8.P15 | length 9.7
  Top Layer w0.2: v1@61.394,50.394 cw(c61.045,50.045) 61.539,50.045 ; v1(61.5,50.5) 61.539,50.461 61.539,49.461 U8.P15@62,49 ; 61.539,50.231 cw(c61.769,50.231) v1@61.606,50.394
  Bottom Layer w0.15: v1@61.442,50.665 ccw(c61.394,50.801) 61.539,50.801 ; v1(61.5,50.5) 61.539,50.539 61.539,50.801 ; v1@61.525,50.5 cw(c62.22,50.5) R67.2@61.729,50.991 ; v1@61.615,50.632 cw(c61.764,50.801) 61.539,50.801 ; v1@61.675,50.5 cw(c62.732,50.5) R67.2@61.985,51.247 ; R67.2@62,51.25 62.75,52 65.1,52 65.566,51.534 R24.2@65.566,50.896 ; R67.2@62.004,51.266 61.539,50.801
NetR39_2: R39.2 R40.2 X4.17 | length 20.6
  Bottom Layer w0.15: X4.17@3.325,57.351 4.374,58.4 R40.2@4.95,58.4
  Bottom Layer w0.2: X4.17@3.325,41.222 4.447,40.1 R39.2@5.25,40.1
  Bottom Layer w1: X4.17@3.325,41.222 X4.17@3.325,57.351
NetR41_1: R41.1 X4.14 | length 1.5
  Bottom Layer w0.15: X4.14@26.82,45.794 26.826,45.8 R41.1@28.35,45.8
NetR42_1: R42.1 X4.15 | length 1.5
  Bottom Layer w0.15: X4.15@26.82,52.906 26.826,52.9 R42.1@28.35,52.9
NetR43_1: R43.1 X4.13 | length 2.5
  Bottom Layer w0.15: X4.13@26.82,43.254 27.324,42.75 27.7,42.75 28.3,42.15 R43.1@28.3,41.55
NetR44_1: R44.1 X4.16 | length 1.6
  Bottom Layer w0.15: X4.16@26.82,55.446 26.866,55.4 R44.1@28.45,55.4
NetR45_2: R45.2 U9.25 X4.11 | length 14.9
  Top Layer w0.15: X4.11@24.28,53.414 24.28,53.22 25.95,51.55 28.1,51.55 28.825,52.275 33.6,52.275 U9.25@33.625,52.3
  Bottom Layer w0.15: R45.2@23,57.25 23,55.55 23.3,55.25 23.3,54.394 X4.11@24.28,53.414
NetR47_2: R47.2 U9.26 X4.10 | length 16.7
  Top Layer w0.15: X4.10@24.28,51.382 24.462,51.2 28.25,51.2 28.95,51.9 U9.26@33.625,51.9
  Bottom Layer w0.15: R47.2@21.6,57.25 21.6,56.25 22.95,54.9 22.95,52.712 X4.10@24.28,51.382
NetR48_2: R48.2 U9.28 X4.4 | length 13.9
  Top Layer w0.15: X4.4@21.74,50.366 21.749,50.375 28.725,50.375 29.45,51.1 U9.28@33.625,51.1
  Bottom Layer w0.15: R48.2@20.15,50.1 21.474,50.1 X4.4@21.74,50.366
NetR49_2: R49.2 U9.29 X4.5 | length 17
  Top Layer w0.15: v2(22.95,49.95) 23,50 28.95,50 29.65,50.7 U9.29@33.625,50.7 ; v2@23.074,49.826 cw(c23.493,49.407) 23.493,50 ; v2@23.074,50.074 ccw(c23.252,50.252) 23.252,50
  Bottom Layer w0.15: R49.2@20.15,52.8 21.338,52.8 X4.5@21.74,52.398 22.95,51.188 v2(22.95,49.95) ; v2@22.826,50.074 ccw(c22.528,50.372) 22.95,50.372 ccw(c23.372,50.372) v2@23.074,50.074
NetR50_2: R50.2 U9.34 X4.3 | length 13.8
  Top Layer w0.15: X4.3@21.74,48.334 22.106,48.7 U9.34@33.625,48.7
  Bottom Layer w0.15: R50.2@20.15,48.7 21.374,48.7 X4.3@21.74,48.334
NetR51_2: R51.2 U9.35 X4.2 | length 14.5
  Top Layer w0.15: X4.2@21.74,46.302 21.752,46.302 23.75,48.3 U9.35@33.625,48.3
  Bottom Layer w0.15: R51.2@20.15,45.8 20.9,45.8 21.402,46.302 X4.2@21.74,46.302
NetR52_2: R52.2 U9.16 | length 2.9
  Top Layer w0.15: U9.16@36.5,54.375 36.5,54.95 37.25,55.7 37.9,55.7 38.05,55.85 R52.2@38.05,56.25
NetR53_2: R53.2 U9.17 | length 2.5
  Top Layer w0.15: U9.17@36.1,54.375 36.1,55.15 36.85,55.9 36.85,56.2 R53.2@37.1,56.45
NetR54_2: R54.2 U9.18 | length 2.2
  Top Layer w0.15: U9.18@35.7,54.375 35.7,56.25 R54.2@35.9,56.45
NetR55_2: R55.2 U9.44 | length 1.8
  Top Layer w0.15: R55.2@34.55,43 34.55,43.65 34.9,44 U9.44@34.9,44.625
NetR56_2: R56.2 U9.13 | length 3.3
  Top Layer w0.15: U9.13@37.7,54.375 37.7,55 38.4,55.7 39.2,55.7 39.35,55.85 39.35,56.3 R56.2@39.5,56.45
NetR57_2: R57.2 U9.49 | length 6.2
  Top Layer w0.15: R57.2@34.5,40.275 36.025,40.275 36.9,41.15 U9.49@36.9,44.625
NetR58_2: R58.2 U9.37 X4.8 | length 14.9
  Top Layer w0.15: X4.8@24.28,45.286 26.894,47.9 28.75,47.9 29.15,47.5 U9.37@33.625,47.5
  Bottom Layer w0.15: R58.2@23,41.55 23,43.45 23.25,43.7 23.25,44.256 X4.8@24.28,45.286
NetR59_2: R59.2 U9.38 X4.9 | length 17.5
  Top Layer w0.15: v2(27.95,47.35) 28.2,47.1 ; v2@27.973,47.177 cw(c28.009,46.909) 28.2,47.1 ; v2@28.123,47.327 ccw(c28.391,47.291) 28.2,47.1 ; U9.38@33.625,47.1 28.2,47.1
  Bottom Layer w0.15: R59.2@21.6,41.55 21.6,42.6 22.85,43.85 22.85,45.888 X4.9@24.28,47.318 24.312,47.35 v2(27.95,47.35) ; v2@27.826,47.226 ccw(c27.528,46.928) 27.528,47.35 ccw(c27.528,47.772) v2@27.826,47.474
NetR60_1: R60.1 U9.32 | length 2.9
  Top Layer w0.15: v2(32.85,49.5) U9.32@33.625,49.5 ; v2@32.974,49.376 cw(c33.272,49.078) 33.272,49.5 cw(c33.272,49.922) v2@32.974,49.624
  Bottom Layer w0.15: R60.1@32.05,49.5 v2(32.85,49.5) ; v2@32.726,49.376 ccw(c32.428,49.078) 32.428,49.5 ccw(c32.428,49.922) v2@32.726,49.624
NetR61_1: R61.1 U9.51 | length 4.3
  Top Layer w0.15: v2@37.626,43.774 ccw(c37.448,43.952) 37.7,43.952 ; 37.7,44.193 ccw(c38.293,44.193) v2@37.874,43.774 ; U9.51@37.7,44.625 37.7,43.7 v2(37.75,43.65)
  Bottom Layer w0.15: R61.1@37.55,42.777 cw(c38.579,42.777) v2@37.87,43.523 ; R61.1@37.55,42.8 37.55,43.45 v2(37.75,43.65) ; 37.55,43.126 cw(c38.247,43.126) v2@37.767,43.632 ; 37.55,43.475 cw(c37.916,43.475) v2@37.664,43.741
NetR62_2: R62.2 R64.1 U10.1 | length 3.8
  Top Layer w0.2: U10.1@33.49,64.5 33.49,64.26 34,63.75 35.2,63.75 R62.2@35.45,63.5 35.5,63.45 R64.1@35.5,62.2
NetR63_1: R63.1 U10.3 | length 2
  Top Layer w0.15: R63.1@26.55,60.55 27.96,60.55 U10.3@28.41,60.1
NetR63_2: R63.2 R78.1 U9.22 | length 11.3
  Top Layer w0.15: R78.1@25.35,59.05 R63.2@26.55,59.05 26.55,57.8 30.85,53.5 U9.22@33.625,53.5
NetR65_2: R65.2 R66.2 U4.7 | length 18.8
  Top Layer w0.15: R65.2@150.1,95.4 150.1,103.65 154.9,108.45 157.99,108.45 R66.2@158.45,108.91
NetR90_2: R90.2 U9.59 | length 5
  Top Layer w0.15: U9.59@40.9,44.625 40.9,43.7 42.25,42.35 R90.2@44.4,42.35
NetR93_1: R93.1 U8.A3 | length 3
  Top Layer w0.15: v2@73.876,35.424 ccw(c73.578,35.722) 74,35.722 ccw(c74.422,35.722) v2@74.124,35.424 ; v2(74,35.3) U8.A3@74,36
  Bottom Layer w0.15: v2@74,35.125 cw(c74,34.944) 74.128,35.072 ; v2(74,35.3) 74,35.2 R93.1@74.6,34.6 ; v2@74.175,35.3 ccw(c74.839,35.3) R93.1@74.369,34.831
NetR96-1_2: R96-1.2 R99-1.1 U30-1.1 | length 3.3
  Top Layer w0.5: R96-1.2@146.489,13.152 146.584,13.057 R99-1.1@146.584,11.866 147.702,11.866 U30-1.1@148.338,12.502
NetR96-2_2: R96-2.2 R99-2.1 U30-2.1 | length 3.3
  Top Layer w0.5: R96-2.2@146.239,62.647 146.334,62.553 146.334,61.361 147.452,61.361 U30-2.1@148.088,61.997
NetR97-1_2: R97-1.2 R100-1.1 U31-1.1 | length 3.9
  Top Layer w0.5: R100-1.1@146.59,20.577 146.59,21.977 148.14,21.977 U31-1.1@148.79,21.327
NetR97-2_2: R97-2.2 R100-2.1 U31-2.1 | length 2.9
  Top Layer w0.5: R97-2.2@146.45,71.2 R97-2.2@146.55,71.2 ; R100-2.1@146.55,69.9 R97-2.2@146.55,71.2 ; R97-2.2@146.55,71.3 R97-2.2@146.55,71.2 ; U31-2.1@148,71.2 R97-2.2@146.55,71.2
NetR98-1_2: R98-1.2 R101-1.1 U32-1.1 | length 4.7
  Top Layer w0.5: R101-1.1@146.542,37.306 146.542,38.578 ; R98-1.2@146.55,39.65 146.542,39.642 146.542,38.578 ; U32-1.1@148.74,38.456 148.74,38.578 146.542,38.578
NetR98-2_2: R98-2.2 R101-2.1 U32-2.1 | length 3.6
  Top Layer w0.5: R101-2.1@146.352,86.35 146.352,87.622 148.55,87.622 U32-2.1@148.55,87.5
NetR102-1_2: R102-1.2 U12-1.18 | length 3.8
  Top Layer w0.2: U12-1.18@120.207,19.638 v4@120.632,19.638 ; v4@120.586,19.567 ccw(c120.416,19.397) 120.416,19.638 ccw(c120.416,19.879) v4@120.586,19.709
  Bottom Layer w0.2: R102-1.2@118.061,19.658 118.081,19.638 v4(120.657,19.638) ; v4@120.586,19.567 ccw(c120.416,19.397) 120.416,19.638 ccw(c120.416,19.879) v4@120.586,19.709
NetR102-2_2: R102-2.2 U12-2.18 | length 3.8
  Top Layer w0.2: U12-2.18@120.246,68.93 v4@120.671,68.93 ; v4@120.625,68.859 ccw(c120.455,68.688) 120.455,68.93 ccw(c120.455,69.171) v4@120.625,69.001
  Bottom Layer w0.2: R102-2.2@118.1,68.95 118.12,68.93 v4(120.696,68.93) ; v4@120.625,68.859 ccw(c120.455,68.688) 120.455,68.93 ccw(c120.455,69.171) v4@120.625,69.001
NetR104-1_2: R104-1.2 U12-1.72 | length 4.5
  Top Layer w0.2: v4@127.282,20.138 U12-1.72@127.707,20.138 ; v4@127.328,20.067 cw(c127.498,19.897) 127.498,20.138 cw(c127.498,20.379) v4@127.328,20.209
  Bottom Layer w0.2: v4(127.257,20.138) 129.112,20.138 129.512,19.738 R104-1.2@130.407,19.738 ; v4@127.328,20.067 cw(c127.498,19.897) 127.498,20.138 cw(c127.498,20.379) v4@127.328,20.209
NetR104-2_2: R104-2.2 U12-2.72 | length 4.5
  Top Layer w0.2: v4@127.321,69.43 U12-2.72@127.746,69.43 ; v4@127.367,69.359 cw(c127.537,69.188) 127.537,69.43 cw(c127.537,69.671) v4@127.367,69.501
  Bottom Layer w0.2: v4(127.296,69.43) 130.046,69.43 R104-2.2@130.446,69.03 ; v4@127.367,69.359 cw(c127.537,69.188) 127.537,69.43 cw(c127.537,69.671) v4@127.367,69.501
NetR105-1_2: R105-1.2 U12-1.73 | length 2.2
  Top Layer w0.2: U12-1.73@128.282,20.388 130.232,20.388 R105-1.2@130.407,20.563
NetR105-2_2: R105-2.2 U12-2.73 | length 2.2
  Top Layer w0.2: U12-2.73@128.321,69.68 130.271,69.68 R105-2.2@130.446,69.855
NetR107-1_2: R107-1.2 R114-1.1 | length 1.3
  Bottom Layer w0.2: R107-1.2@118.211,13.108 R114-1.1@119.461,13.108
NetR107-2_2: R107-2.2 R114-2.1 | length 1.3
  Bottom Layer w0.2: R107-2.2@118.25,62.4 R114-2.1@119.5,62.4
NetR108-1_2: R108-1.2 U12-1.89 | length 9.4
  Top Layer w0.2: v4@127.136,23.759 ccw(c126.966,23.93) 127.207,23.93 ccw(c127.448,23.93) v4@127.278,23.759 ; v4@127.207,23.713 U12-1.89@127.207,24.138 ; v1(129.561,28.558) 130.311,28.558 R108-1.2@130.461,28.408 ; v1@129.649,28.47 cw(c129.863,28.256) 129.863,28.558 cw(c129.863,28.86) v1@129.649,28.647
  MidLayer1 w0.2: v4(127.207,23.688) 128.061,24.542 128.061,27.858 128.761,28.558 v1(129.561,28.558) ; v4@127.207,23.788 ccw(c127.207,24.03) 127.378,23.859 ccw(c127.548,23.688) v4@127.307,23.688 ; v1@129.473,28.47 ccw(c129.259,28.256) 129.259,28.558 ccw(c129.259,28.86) v1@129.473,28.647
NetR108-2_2: R108-2.2 U12-2.89 | length 9.4
  Top Layer w0.2: v4@127.175,73.051 ccw(c127.005,73.221) 127.246,73.221 ccw(c127.487,73.221) v4@127.317,73.051 ; v4@127.246,73.005 U12-2.89@127.246,73.43 ; v1(129.6,77.85) 130.35,77.85 R108-2.2@130.5,77.7 ; v1@129.688,77.762 cw(c129.902,77.548) 129.902,77.85 cw(c129.902,78.152) v1@129.688,77.938
  MidLayer1 w0.2: v4(127.246,72.98) 128.1,73.834 128.1,77.15 128.8,77.85 v1(129.6,77.85) ; v4@127.246,73.08 ccw(c127.246,73.321) 127.417,73.151 ccw(c127.587,72.98) v4@127.346,72.98 ; v1@129.512,77.762 ccw(c129.298,77.548) 129.298,77.85 ccw(c129.298,78.152) v1@129.512,77.938
NetR110-1_2: R110-1.2 U12-1.52 | length 10.9
  Top Layer w0.2: v1@125.483,15.439 ccw(c125.574,15.662) 125.744,15.491 ; v1(125.511,15.508) 125.761,15.508 ; v1@125.558,15.624 ccw(c125.697,15.964) 125.957,15.704 ; v1@125.611,15.433 cw(c125.761,15.321) 125.761,15.508 ; v1@125.611,15.583 ccw(c125.761,15.696) 125.761,15.508 ; U12-1.52@125.957,16.063 125.957,15.704 ; 125.761,15.508 125.957,15.704
  Bottom Layer w0.2: v1@125.423,15.42 cw(c125.209,15.206) 125.511,15.206 cw(c125.813,15.206) v1@125.599,15.42 ; v1(125.511,15.508) 125.511,15.158 126.161,14.508 126.161,11.908 128.911,9.158 R110-1.2@129.611,9.158
NetR110-2_2: R110-2.2 U12-2.52 | length 10.9
  Top Layer w0.2: v1@125.522,64.731 ccw(c125.613,64.954) 125.783,64.783 ; v1(125.55,64.8) 125.8,64.8 ; v1@125.597,64.916 ccw(c125.736,65.256) 125.996,64.996 ; v1@125.65,64.725 cw(c125.8,64.613) 125.8,64.8 ; v1@125.65,64.875 ccw(c125.8,64.987) 125.8,64.8 ; U12-2.52@125.996,65.355 125.996,64.996 ; 125.8,64.8 125.996,64.996
  Bottom Layer w0.2: v1@125.462,64.712 cw(c125.248,64.498) 125.55,64.498 cw(c125.852,64.498) v1@125.638,64.712 ; v1(125.55,64.8) 125.55,64.45 126.2,63.8 126.2,61.2 128.95,58.45 R110-2.2@129.65,58.45
NetR111-1_2: R111-1.2 U12-1.51 | length 9.9
  Top Layer w0.2: v4@125.636,17.017 cw(c125.466,16.847) 125.707,16.847 cw(c125.948,16.847) v4@125.778,17.017 ; U12-1.51@125.707,16.638 v4@125.707,17.063
  Bottom Layer w0.2: v4@125.636,17.017 cw(c125.466,16.847) 125.707,16.847 cw(c125.948,16.847) v4@125.778,17.017 ; v4(125.707,17.088) 125.707,15.913 125.936,15.684 125.936,15.157 126.561,14.532 126.561,12.758 129.031,10.288 R111-1.2@129.607,10.288
NetR111-2_2: R111-2.2 U12-2.51 | length 9.9
  Top Layer w0.2: v4@125.675,66.309 cw(c125.505,66.138) 125.746,66.138 cw(c125.987,66.138) v4@125.817,66.309 ; U12-2.51@125.746,65.93 v4@125.746,66.355
  Bottom Layer w0.2: v4@125.675,66.309 cw(c125.505,66.138) 125.746,66.138 cw(c125.987,66.138) v4@125.817,66.309 ; v4(125.746,66.38) 125.746,65.205 125.975,64.976 125.975,64.449 126.6,63.824 126.6,62.05 129.07,59.58 R111-2.2@129.646,59.58
NetR112-1_2: R112-1.2 U12-1.54 | length 7.3
  Top Layer w0.2: v1@126.323,15.597 ccw(c125.998,15.921) U12-1.54@126.457,15.921 ; v1(126.411,15.508) 126.311,15.508 126.457,15.654 U12-1.54@126.457,16.063
  Bottom Layer w0.2: v1(126.411,15.508) 126.411,15.439 128.1,13.75 128.1,12.068 128.58,11.588 R112-1.2@129.607,11.588 ; v1@126.536,15.508 ccw(c127.005,15.508) 126.673,15.177
NetR112-2_2: R112-2.2 U12-2.54 | length 7.4
  Top Layer w0.2: v1@126.362,64.888 ccw(c126.037,65.213) U12-2.54@126.496,65.213 ; v1(126.45,64.8) 126.35,64.8 126.496,64.946 U12-2.54@126.496,65.355
  Bottom Layer w0.2: v1@126.362,64.712 cw(c126.148,64.498) 126.45,64.498 cw(c126.752,64.498) v1@126.538,64.712 ; v1(126.45,64.8) 126.45,64.399 126.9,63.949 126.9,62.599 128.619,60.88 R112-2.2@129.646,60.88
NetR113-1_2: R113-1.2 U12-1.56 | length 5.6
  Top Layer w0.2: v1@126.873,15.597 ccw(c126.669,15.8) 126.957,15.8 ; 126.957,15.82 ccw(c127.273,15.82) v1@127.049,15.597 ; U12-1.56@126.957,16.063 126.957,15.512 v1(126.961,15.508)
  Bottom Layer w0.2: v1@126.961,15.383 cw(c126.961,15.081) 127.174,15.295 cw(c127.388,15.508) v1@127.086,15.508 ; v1(126.961,15.508) 128.661,13.808 128.661,13.208 128.981,12.888 R113-1.2@129.607,12.888
NetR113-2_2: R113-2.2 U12-2.56 | length 5.9
  Top Layer w0.2: v1@126.912,64.888 ccw(c126.708,65.092) 126.996,65.092 ; 126.996,65.112 ccw(c127.312,65.112) v1@127.088,64.888 ; U12-2.56@126.996,65.355 126.996,64.804 v1(127,64.8)
  Bottom Layer w0.2: v1(127,64.8) 127.45,64.8 128.7,63.55 128.7,62.5 129.02,62.18 R113-2.2@129.646,62.18 ; v1@127.088,64.712 cw(c127.302,64.498) 127.302,64.8 cw(c127.302,65.102) v1@127.088,64.888
NetR114-1_2: R114-1.2 U12-1.39 | length 7.5
  Top Layer w0.2: v4@122.636,17.017 cw(c122.466,16.847) 122.707,16.847 cw(c122.948,16.847) v4@122.778,17.017 ; U12-1.39@122.707,16.638 v4@122.707,17.063
  Mid-Layer 2 w0.2: v1(119.511,13.858) 119.477,13.858 122.307,16.688 122.373,16.688 122.707,17.022 v4(122.707,17.088) ; v1@119.511,13.983 ccw(c119.511,14.203) 119.667,14.048 ; v1@119.636,13.858 cw(c120.02,13.858) 119.748,14.129 ; 122.49,16.805 ccw(c122.207,17.088) v4@122.607,17.088
  Bottom Layer w0.2: v1@119.423,13.947 ccw(c119.209,14.16) 119.511,14.16 ccw(c119.813,14.16) v1@119.599,13.947 ; R114-1.2@119.461,14.608 119.511,14.558 v1(119.511,13.858)
NetR114-2_2: R114-2.2 U12-2.39 | length 7.5
  Top Layer w0.2: v4@122.675,66.309 cw(c122.505,66.138) 122.746,66.138 cw(c122.987,66.138) v4@122.817,66.309 ; U12-2.39@122.746,65.93 v4@122.746,66.355
  Mid-Layer 2 w0.2: v1(119.55,63.15) 119.516,63.15 122.346,65.98 122.412,65.98 122.746,66.314 v4(122.746,66.38) ; v1@119.55,63.275 ccw(c119.55,63.495) 119.706,63.339 ; v1@119.675,63.15 cw(c120.059,63.15) 119.787,63.421 ; 122.529,66.097 ccw(c122.246,66.38) v4@122.646,66.38
  Bottom Layer w0.2: v1@119.462,63.238 ccw(c119.248,63.452) 119.55,63.452 ccw(c119.852,63.452) v1@119.638,63.238 ; R114-2.2@119.5,63.9 119.55,63.85 v1(119.55,63.15)
NetR115-1_1: R115-1.1 U12-1.116 | length 4.6
  Top Layer w0.15: R115-1.1@116.761,26.258 116.761,25.858 117.169,25.45 118.272,25.45 119.01,24.713 U12-1.116@120.457,24.713
NetR115-1_2: R115-1.2 R120-1.2 U13-1.8 | length 7.1
  Top Layer w0.15: v1(116.811,28.708) 117.311,29.208 118.661,29.208 118.961,29.508 119.261,29.508 119.561,29.808 119.661,29.808 119.716,29.863 U13-1.8@119.716,30.661 ; v1@116.811,28.858 ccw(c116.811,29.22) 117.067,28.964 ccw(c117.323,28.708) v1@116.961,28.708
  Top Layer w0.2: R115-1.2@116.611,27.958 116.811,28.158 v1(116.811,28.708) ; R115-1.2@116.661,27.958 R115-1.2@116.816,28.113
  Bottom Layer w0.2: R120-1.2@116.661,27.958 116.811,28.108 v1(116.811,28.708) ; v1@116.723,28.62 cw(c116.509,28.406) 116.811,28.406 cw(c117.113,28.406) v1@116.899,28.62
NetR115-2_1: R115-2.1 U12-2.116 | length 4.6
  Top Layer w0.15: R115-2.1@116.8,75.55 116.8,75.15 117.208,74.742 118.311,74.742 119.049,74.005 U12-2.116@120.496,74.005
NetR115-2_2: R115-2.2 R120-2.2 U13-2.8 | length 7.1
  Top Layer w0.15: R115-2.2@116.65,77.25 R115-2.2@116.85,77.45 ; v1(116.85,78) 117.175,78.325 117.664,78.325 117.839,78.5 118.7,78.5 119,78.8 119.3,78.8 119.6,79.1 119.7,79.1 119.755,79.155 U13-2.8@119.755,79.953 ; v1@116.85,78.15 ccw(c116.85,78.512) 117.106,78.256 ccw(c117.362,78) v1@117,78
  Top Layer w0.2: R115-2.2@116.7,77.25 R115-2.2@116.855,77.405 ; R115-2.2@116.85,77.45 v1(116.85,78)
  Bottom Layer w0.2: R120-2.2@116.7,77.25 116.85,77.4 v1(116.85,78) ; v1@116.762,77.912 cw(c116.548,77.698) 116.85,77.698 cw(c117.152,77.698) v1@116.938,77.912
NetR116-1_1: R116-1.1 U12-1.115 | length 6.6
  Top Layer w0.15: R116-1.1@115.461,26.458 115.461,25.858 116.119,25.2 118.169,25.2 118.961,24.408 120.011,24.408 120.281,24.138 U12-1.115@120.707,24.138
NetR116-1_2: R116-1.2 R122-1.1 U13-1.1 | length 15.1
  Top Layer w0.2: v1@115.373,28.62 cw(c115.159,28.406) 115.461,28.406 cw(c115.763,28.406) v1@115.549,28.62 ; R116-1.2@115.461,27.958 v1@115.461,28.658 ; v1(119.061,34.008) 119.261,34.208 ; v1@119.061,34.133 ccw(c119.061,34.556) 119.36,34.257 ; v1@119.067,34.133 ccw(c119.079,34.39) 119.261,34.208 ; v1@119.111,34.008 119.311,34.208 ; v1@119.186,34.014 cw(c119.443,34.026) 119.261,34.208 ; U13-1.1@119.711,36.255 119.711,34.608 119.311,34.208 ; 119.261,34.208 119.311,34.208 ; 119.311,34.208 cw(c119.12,34.4) 119.08,34.132 ccw(c119.12,34.4) 119.311,34.208
  Bottom Layer w0.2: v1@115.373,28.62 cw(c115.159,28.406) 115.461,28.406 cw(c115.763,28.406) v1@115.549,28.62 ; v1@115.373,28.797 ccw(c115.159,29.01) 115.461,29.01 ccw(c115.763,29.01) v1@115.549,28.797 ; R122-1.1@115.461,27.958 v1(115.461,28.708) 115.461,31.958 117.511,34.008 v1(119.061,34.008) ; v1@118.973,33.92 ccw(c118.759,33.706) 118.759,34.008 ccw(c118.759,34.31) v1@118.973,34.097
NetR116-2_1: R116-2.1 U12-2.115 | length 6.6
  Top Layer w0.15: R116-2.1@115.5,75.75 115.5,75.15 116.158,74.492 118.208,74.492 119,73.7 120.05,73.7 120.32,73.43 U12-2.115@120.746,73.43
NetR116-2_2: R116-2.2 R122-2.1 U13-2.1 | length 17.8
  Top Layer w0.2: v1@115.412,77.912 cw(c115.198,77.698) 115.5,77.698 cw(c115.802,77.698) v1@115.588,77.912 ; R116-2.2@115.5,77.25 v1@115.5,77.95 ; v1(115.5,78) 116.1,78.6 117.55,78.6 117.8,78.85 117.8,81.45 v2(116.85,82.4) ; v1@115.5,78.125 ccw(c115.5,78.427) 115.713,78.213 ccw(c115.927,78) v1@115.625,78 ; v2@116.85,82.25 cw(c116.85,81.888) 117.106,82.144 cw(c117.362,82.4) v2@117,82.4 ; v1(119.1,83.3) 119.3,83.5 ; v1@119.1,83.425 ccw(c119.1,83.847) 119.399,83.549 ; v1@119.106,83.425 ccw(c119.118,83.682) 119.3,83.5 ; v1@119.15,83.3 119.35,83.5 ; v1@119.225,83.306 cw(c119.482,83.318) 119.3,83.5 ; U13-2.1@119.75,85.547 119.75,83.9 119.35,83.5 ; 119.3,83.5 119.35,83.5 ; 119.35,83.5 cw(c119.158,83.692) 119.118,83.424 ccw(c119.158,83.692) 119.35,83.5
  Bottom Layer w0.2: v1@115.412,77.912 cw(c115.198,77.698) 115.5,77.698 cw(c115.802,77.698) v1@115.588,77.912 ; R122-2.1@115.5,77.25 v1(115.5,78) ; v2(116.85,82.4) 117.75,83.3 v1(119.1,83.3) ; v2@116.85,82.55 ccw(c116.85,82.912) 117.106,82.656 ccw(c117.362,82.4) v2@117,82.4 ; v1@119.012,83.212 ccw(c118.798,82.998) 118.798,83.3 ccw(c118.798,83.602) v1@119.012,83.388
NetR117-1_1: R117-1.1 U12-1.113 | length 5.8
  Top Layer w0.2: R117-1.1@119.011,26.458 119.211,26.258 v1(119.211,25.658) ; v1@119.123,25.747 ccw(c118.909,25.96) 119.211,25.96 ccw(c119.513,25.96) v1@119.299,25.747 ; v4@121.136,23.759 ccw(c120.966,23.93) 121.207,23.93 ccw(c121.448,23.93) v4@121.278,23.759 ; v4@121.207,23.713 U12-1.113@121.207,24.138
  Mid-Layer 2 w0.2: v1@119.211,25.533 cw(c119.211,25.169) 119.469,25.427 ; v1@119.237,25.658 v4(121.207,23.688) ; v1@119.336,25.658 ccw(c119.575,25.658) 119.406,25.489 ; v4@121.107,23.688 ccw(c120.866,23.688) 121.036,23.859 ccw(c121.207,24.03) v4@121.207,23.788
  MidLayer1 w0.2: v1(119.211,25.658) v1@119.237,25.658
NetR117-1_2: R117-1.2 R123-1.2 U14-1.8 | length 10.7
  Top Layer w0.15: v1@119.267,28.652 cw(c119.765,28.155) 119.765,28.858 ; 119.402,28.858 ccw(c119.402,28.517) v1(119.161,28.758) 119.261,28.858 122.911,28.858 123.161,29.108 124.461,29.108 125.266,29.913 U14-1.8@125.266,30.711
  Top Layer w0.2: v1@119.073,28.67 cw(c118.859,28.456) 119.161,28.456 cw(c119.463,28.456) v1@119.249,28.67 ; R117-1.2@119.161,27.958 v1@119.161,28.708
  Bottom Layer w0.2: v1@119.073,28.67 cw(c118.859,28.456) 119.161,28.456 cw(c119.463,28.456) v1@119.249,28.67 ; R123-1.2@119.161,27.958 v1(119.161,28.758)
NetR117-2_1: R117-2.1 U12-2.113 | length 5.8
  Top Layer w0.2: R117-2.1@119.05,75.75 119.25,75.55 v1(119.25,74.95) ; v1@119.162,75.038 ccw(c118.948,75.252) 119.25,75.252 ccw(c119.552,75.252) v1@119.338,75.038 ; v4@121.175,73.051 ccw(c121.005,73.221) 121.246,73.221 ccw(c121.487,73.221) v4@121.317,73.051 ; v4@121.246,73.005 U12-2.113@121.246,73.43
  Mid-Layer 2 w0.2: v1@119.25,74.825 cw(c119.25,74.461) 119.508,74.718 ; v1@119.276,74.95 v4(121.246,72.98) ; v1@119.375,74.95 ccw(c119.614,74.95) 119.445,74.781 ; v4@121.146,72.98 ccw(c120.905,72.98) 121.075,73.151 ccw(c121.246,73.321) v4@121.246,73.08
  MidLayer1 w0.2: v1(119.25,74.95) v1@119.276,74.95
NetR117-2_2: R117-2.2 R123-2.2 U14-2.8 | length 10.7
  Top Layer w0.15: v1@119.306,77.944 cw(c119.804,77.446) 119.804,78.15 ; 119.441,78.15 ccw(c119.441,77.809) v1(119.2,78.05) 119.3,78.15 122.95,78.15 123.2,78.4 124.5,78.4 125.305,79.205 U14-2.8@125.305,80.003
  Top Layer w0.2: v1@119.112,77.962 cw(c118.898,77.748) 119.2,77.748 cw(c119.502,77.748) v1@119.288,77.962 ; R117-2.2@119.2,77.25 v1@119.2,78
  Bottom Layer w0.2: v1@119.112,77.962 cw(c118.898,77.748) 119.2,77.748 cw(c119.502,77.748) v1@119.288,77.962 ; R123-2.2@119.2,77.25 v1(119.2,78.05)
NetR118-1_1: R118-1.1 U12-1.114 | length 4.5
  Top Layer w0.15: R118-1.1@117.761,26.458 117.761,25.808 117.869,25.7 118.376,25.7 118.818,25.258 120.761,25.258 120.957,25.062 U12-1.114@120.957,24.713
NetR118-1_2: R118-1.2 R124-1.1 U14-1.1 | length 17
  Top Layer w0.15: v1(117.961,28.758) 118.565,28.758 118.965,29.158 122.661,29.158 122.861,29.358 124.261,29.358 124.611,29.708 124.611,32.358 125.261,33.008 U14-1.1@125.261,36.305 ; v1@118.067,28.652 cw(c118.323,28.396) 118.323,28.758 cw(c118.323,29.12) v1@118.067,28.864
  Top Layer w0.2: v1@117.873,28.67 cw(c117.659,28.456) 117.961,28.456 cw(c118.263,28.456) v1@118.049,28.67 ; R118-1.2@117.961,27.958 v1@117.961,28.708
  Bottom Layer w0.2: v1@117.873,28.67 cw(c117.659,28.456) 117.961,28.456 cw(c118.263,28.456) v1@118.049,28.67 ; R124-1.1@117.961,27.958 v1(117.961,28.758)
NetR118-2_1: R118-2.1 U12-2.114 | length 4.5
  Top Layer w0.15: R118-2.1@117.8,75.75 117.8,75.1 117.908,74.992 118.415,74.992 118.857,74.55 120.8,74.55 120.996,74.354 U12-2.114@120.996,74.005
NetR118-2_2: R118-2.2 R124-2.1 U14-2.1 | length 17
  Top Layer w0.15: v1(118,78.05) 118.604,78.05 119.004,78.45 122.7,78.45 122.9,78.65 124.3,78.65 124.65,79 124.65,81.65 125.3,82.3 U14-2.1@125.3,85.597 ; v1@118.106,77.944 cw(c118.362,77.688) 118.362,78.05 cw(c118.362,78.412) v1@118.106,78.156
  Top Layer w0.2: v1@117.912,77.962 cw(c117.698,77.748) 118,77.748 cw(c118.302,77.748) v1@118.088,77.962 ; R118-2.2@118,77.25 v1@118,78
  Bottom Layer w0.2: v1@117.912,77.962 cw(c117.698,77.748) 118,77.748 cw(c118.302,77.748) v1@118.088,77.962 ; R124-2.1@118,77.25 v1(118,78.05)
NetR125-1_1: R125-1.1 U12-1.100 | length 5.6
  Top Layer w0.15: v1@123.955,27.264 ccw(c123.699,27.52) 124.061,27.52 ccw(c124.423,27.52) v1@124.167,27.264 ; v1(124.061,27.158) R125-1.1@124.061,27.858 ; v1@124.355,25.252 cw(c124.109,25.006) 124.457,25.006 ; U12-1.100@124.457,24.713 124.457,25.304 124.461,25.308 v1(124.461,25.358) ; 124.457,24.986 cw(c124.833,24.986) v1@124.567,25.252
  Bottom Layer w0.15: v1@123.955,27.052 cw(c123.699,26.796) 124.061,26.796 cw(c124.423,26.796) v1@124.167,27.052 ; v1(124.061,27.158) 124.061,25.758 v1(124.461,25.358) ; v1@124.311,25.358 ccw(c123.949,25.358) 124.205,25.614 ccw(c124.461,25.87) v1@124.461,25.508
NetR125-1_2: R125-1.2 U12-1.102 | length 1.7
  Top Layer w0.15: U12-1.102@123.957,24.713 123.957,26.254 R125-1.2@124.061,26.358
NetR125-2_1: R125-2.1 U12-2.100 | length 5.6
  Top Layer w0.15: v1@123.994,76.556 ccw(c123.738,76.812) 124.1,76.812 ccw(c124.462,76.812) v1@124.206,76.556 ; v1(124.1,76.45) R125-2.1@124.1,77.15 ; v1@124.394,74.544 cw(c124.148,74.298) 124.496,74.298 ; U12-2.100@124.496,74.005 124.496,74.596 124.5,74.6 v1(124.5,74.65) ; 124.496,74.278 cw(c124.872,74.278) v1@124.606,74.544
  Bottom Layer w0.15: v1@123.994,76.344 cw(c123.738,76.088) 124.1,76.088 cw(c124.462,76.088) v1@124.206,76.344 ; v1(124.1,76.45) 124.1,75.05 v1(124.5,74.65) ; v1@124.35,74.65 ccw(c123.988,74.65) 124.244,74.906 ccw(c124.5,75.162) v1@124.5,74.8
NetR125-2_2: R125-2.2 U12-2.102 | length 1.7
  Top Layer w0.15: U12-2.102@123.996,74.005 123.996,75.546 R125-2.2@124.1,75.65
NetR128_2: R128.2 R136.2 U15.5 | length 27.6
  Top Layer w0.3: R136.2@60.7,83 60.7,91.95 62.2,93.45 64.25,93.45 64.8,94 64.8,102.55 63,104.35 61.943,104.35 ; R128.2@61.915,104.8 61.943,104.772 61.943,104.35 ; U15.5@61.943,103.289 61.943,104.35
NetR129_2: R129.2 R137.2 U16.5 | length 24.1
  Top Layer w0.3: R129.2@20.6,105.15 20.6,104.25 ; U16.5@20.605,103.305 20.6,103.31 20.6,104.25 ; R137.2@21.55,85.1 21.55,92.6 23.3,94.35 23.3,103.7 22.7,104.3 20.65,104.3 20.6,104.25
NetR130_2: R130.2 R138.2 U17.5 | length 26.5
  Top Layer w0.2: R138.2@41.15,84.5 41.15,92 42.45,93.3 44,93.3 44.5,93.8 44.5,102.4 42.6,104.3 41.85,104.3
  Top Layer w0.3: v2(41.85,106.25) 41.85,104.3 41.85,103.505 U17.5@41.903,103.452
NetR139_2: R139.2 R141.1 Z2.5 | length 3.4
  Top Layer w0.2: Z2.5@141.251,44.306 R139.2@143.351,44.306 R141.1@144.651,44.306
NetR140_2: R140.2 R142.1 Z3.5 | length 3.4
  Top Layer w0.2: Z3.5@141.301,50.156 144.601,50.156 R142.1@144.651,50.206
